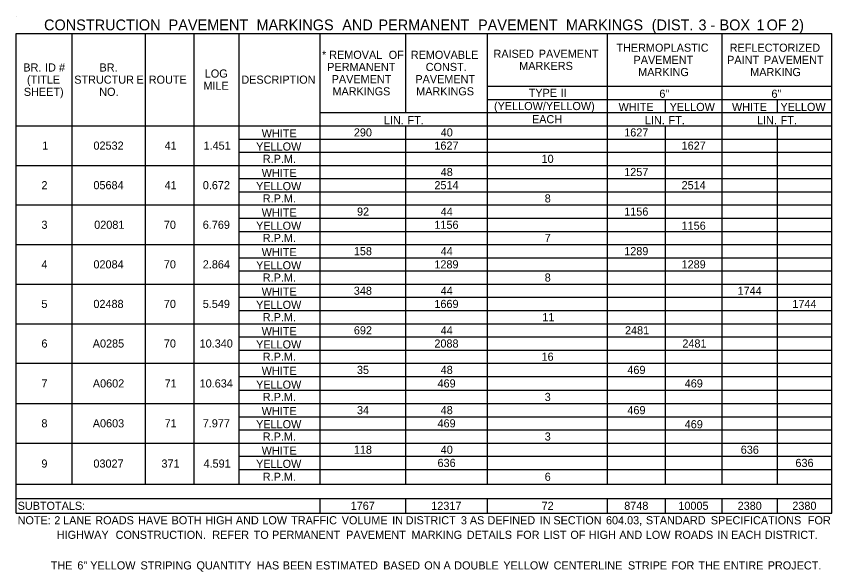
# Model space of a CAD drawing. Extents: x 544478 to 1930787, y -1948294 to 596640.
# Drawn here: x 557631 to 558234, y -1946545 to -1946135 of the extents above; entities that cross this region are included whole.
import ezdxf

# ---------------------------------------------------------------- set-up
doc = ezdxf.new("R2010")
doc.units = 0
doc.layers.add('Default', color=7, linetype='Continuous')

msp = doc.modelspace()

# ---------------------------------------------------------------- linework, layer by layer
at = {"layer": 'Default'}
for p, q in [((557631.45, -1946134.91), (557631.45, -1946134.91)), ((557631.45, -1946147.59), (558234.48, -1946147.59)), ((557631.45, -1946147.59), (557856.18, -1946147.59)), ((557631.45, -1946502), (557631.45, -1946147.59)), ((557672.88, -1946480.55), (557672.88, -1946147.59)), ((557727, -1946480.55), (557727, -1946147.59)), ((557763.07, -1946480.55), (557763.07, -1946147.59)), ((557796.22, -1946480.55), (557796.22, -1946147.59)), ((557856.18, -1946480.55), (557856.18, -1946147.59)), ((557919.56, -1946147.59), (557980.01, -1946147.59)), ((557919.56, -1946206.09), (557919.56, -1946147.59)), ((557980.01, -1946480.55), (557980.01, -1946147.59)), ((558068.73, -1946480.55), (558068.73, -1946147.59)), ((558153.56, -1946215.84), (558153.56, -1946147.59)), ((558153.56, -1946480.55), (558153.56, -1946147.59)), ((558234.48, -1946502), (558234.48, -1946147.59)), ((557980.01, -1946186.59), (558234.48, -1946186.59)), ((557980.01, -1946196.34), (558234.48, -1946196.34)), ((558111.63, -1946206.09), (558111.63, -1946196.34)), ((558194.51, -1946206.09), (558194.51, -1946196.34)), ((557856.18, -1946206.09), (558234.48, -1946206.09)), ((558068.73, -1946264.59), (558068.73, -1946206.09)), ((557631.45, -1946215.84), (557856.18, -1946215.84)), ((557631.45, -1946215.84), (557796.22, -1946215.84)), ((557796.22, -1946215.84), (558234.48, -1946215.84)), ((557919.56, -1946235.34), (557919.56, -1946215.84)), ((557919.56, -1946480.55), (557919.56, -1946215.84)), ((557980.01, -1946215.84), (558234.48, -1946215.84)), ((558111.63, -1946450.32), (558111.63, -1946215.84)), ((558111.63, -1946480.55), (558111.63, -1946215.84)), ((558194.51, -1946450.32), (558194.51, -1946215.84)), ((558194.51, -1946480.55), (558194.51, -1946215.84)), ((557796.22, -1946225.59), (558234.48, -1946225.59)), ((557796.22, -1946480.55), (557796.22, -1946225.59)), ((557856.18, -1946235.34), (557856.18, -1946225.59)), ((557796.22, -1946235.34), (558234.48, -1946235.34)), ((557631.45, -1946245.09), (557980.01, -1946245.09)), ((557796.22, -1946245.09), (557856.18, -1946245.09)), ((557856.18, -1946264.59), (557856.18, -1946245.09)), ((557919.56, -1946245.09), (557980.01, -1946245.09)), ((557919.56, -1946264.59), (557919.56, -1946245.09)), ((557980.01, -1946245.09), (558234.48, -1946245.09)), ((557980.01, -1946264.59), (557980.01, -1946245.09)), ((557796.22, -1946254.84), (558234.48, -1946254.84)), ((557796.22, -1946264.59), (558234.48, -1946264.59)), ((557631.45, -1946274.34), (558234.48, -1946274.34)), ((557796.22, -1946274.34), (557856.18, -1946274.34)), ((557856.18, -1946293.84), (557856.18, -1946274.34)), ((557919.56, -1946293.84), (557919.56, -1946274.34)), ((558068.73, -1946293.84), (558068.73, -1946274.34)), ((557796.22, -1946284.09), (558234.48, -1946284.09)), ((557796.22, -1946293.84), (558234.48, -1946293.84)), ((557631.45, -1946303.59), (558234.48, -1946303.59)), ((557856.18, -1946323.09), (557856.18, -1946303.59)), ((557919.56, -1946323.09), (557919.56, -1946303.59)), ((558068.73, -1946352.34), (558068.73, -1946303.59)), ((557796.22, -1946313.34), (558234.48, -1946313.34)), ((557796.22, -1946323.09), (558234.48, -1946323.09)), ((557631.45, -1946332.84), (557980.01, -1946332.84)), ((557796.22, -1946332.84), (557856.18, -1946332.84)), ((557856.18, -1946352.34), (557856.18, -1946332.84)), ((557919.56, -1946332.84), (557980.01, -1946332.84)), ((557919.56, -1946352.34), (557919.56, -1946332.84)), ((557980.01, -1946332.84), (558234.48, -1946332.84)), ((557796.22, -1946342.59), (558234.48, -1946342.59)), ((557980.01, -1946352.34), (557980.01, -1946342.59)), ((557796.22, -1946352.34), (558234.48, -1946352.34)), ((557631.45, -1946362.09), (558234.48, -1946362.09)), ((557856.18, -1946381.59), (557856.18, -1946362.09)), ((557919.56, -1946381.59), (557919.56, -1946362.09)), ((558068.73, -1946440.57), (558068.73, -1946362.09)), ((557796.22, -1946371.84), (558234.48, -1946371.84)), ((557980.01, -1946381.59), (557980.01, -1946371.84)), ((557796.22, -1946381.59), (558234.48, -1946381.59)), ((557631.45, -1946391.34), (557980.01, -1946391.34)), ((557856.18, -1946411.32), (557856.18, -1946391.34)), ((557919.56, -1946391.34), (557980.01, -1946391.34)), ((557919.56, -1946411.32), (557919.56, -1946391.34)), ((557980.01, -1946391.34), (558234.48, -1946391.34)), ((557796.22, -1946401.09), (558234.48, -1946401.09)), ((557980.01, -1946411.32), (557980.01, -1946401.09)), ((557796.22, -1946411.32), (558234.48, -1946411.32)), ((557631.45, -1946421.07), (557980.01, -1946421.07)), ((557796.22, -1946421.07), (557856.18, -1946421.07)), ((557856.18, -1946440.57), (557856.18, -1946421.07)), ((557919.56, -1946421.07), (557980.01, -1946421.07)), ((557919.56, -1946440.57), (557919.56, -1946421.07)), ((557980.01, -1946421.07), (558234.48, -1946421.07)), ((557796.22, -1946430.82), (558234.48, -1946430.82)), ((557796.22, -1946440.57), (558234.48, -1946440.57)), ((557631.45, -1946450.32), (558234.48, -1946450.32)), ((557856.18, -1946469.82), (557856.18, -1946450.32)), ((557919.56, -1946469.82), (557919.56, -1946450.32)), ((558068.73, -1946480.55), (558068.73, -1946450.32)), ((558153.56, -1946480.55), (558153.56, -1946450.32)), ((557796.22, -1946460.07), (558234.48, -1946460.07)), ((557796.22, -1946469.82), (558234.48, -1946469.82)), ((558111.63, -1946480.55), (558111.63, -1946469.82)), ((558194.51, -1946480.55), (558194.51, -1946469.82)), ((557631.45, -1946480.55), (558234.48, -1946480.55)), ((557919.56, -1946480.55), (557980.01, -1946480.55)), ((557980.01, -1946480.55), (558234.48, -1946480.55)), ((557631.45, -1946491.27), (558234.48, -1946491.27)), ((557856.18, -1946502), (557856.18, -1946491.27)), ((557856.18, -1946502), (557856.18, -1946491.27)), ((557919.56, -1946502), (557919.56, -1946491.27)), ((557919.56, -1946502), (557919.56, -1946491.27)), ((557980.01, -1946502), (557980.01, -1946491.27)), ((557980.01, -1946502), (557980.01, -1946491.27)), ((558068.73, -1946502), (558068.73, -1946491.27)), ((558068.73, -1946502), (558068.73, -1946491.27)), ((558111.63, -1946502), (558111.63, -1946491.27)), ((558111.63, -1946502), (558111.63, -1946491.27)), ((558153.56, -1946502), (558153.56, -1946491.27)), ((558153.56, -1946502), (558153.56, -1946491.27)), ((558194.51, -1946502), (558194.51, -1946491.27)), ((558194.51, -1946502), (558194.51, -1946491.27)), ((557631.45, -1946502), (558234.48, -1946502))]:
    msp.add_line(p, q, dxfattribs=at)

# ---------------------------------------------------------------- texts
for s, height, p in [('CONSTRUCTION', 8, (557651.97, -1946145.25)), (' PAVEMENT', 8, (557741.12, -1946145.25)), (' MARKINGS', 8, (557806.11, -1946145.25)), (' AND', 8, (557869.52, -1946145.25)), (' PERMANENT', 8, (557896.29, -1946145.25)), (' PAVEMENT', 8, (557969.97, -1946145.25)), (' MARKINGS', 8, (558034.96, -1946145.25)), (' (DIST.', 8, (558098.37, -1946145.25)), (' 3', 8, (558132.99, -1946145.25)), (' BOX', 8, (558148.57, -1946145.25)), (' 1', 8, (558175.89, -1946145.25)), (' OF', 8, (558183.4, -1946145.25)), (' 2)', 8, (558201.51, -1946145.25)), (' -', 8, (558141.83, -1946145.25)), ('THERMOPLASTIC', 6, (558075.26, -1946161.09)), ('REFLECTORIZED', 6, (558159.06, -1946161.09)), ('*', 6, (557857.54, -1946166.34)), (' REMOVAL', 6, (557860.62, -1946166.34)), (' OF', 6, (557904.62, -1946166.34)), ('REMOVABLE', 6, (557923.21, -1946166.34)), ('RAISED', 6, (557984.37, -1946165.59)), (' PAVEMENT', 6, (558015.63, -1946165.59)), ('PAVEMENT', 6, (558087.94, -1946170.09)), ('PAINT', 6, (558157.16, -1946170.09)), (' PAVEMENT', 6, (558182.14, -1946170.09)), ('BR.', 6, (557636.64, -1946175.71)), (' ID', 6, (557650.5, -1946175.71)), (' #', 6, (557660.8, -1946175.71)), ('BR.', 6, (557693.01, -1946175.71)), ('PERMANENT', 6, (557861.41, -1946175.34)), ('CONST.', 6, (557934.24, -1946175.34)), ('MARKERS', 6, (558003.38, -1946174.59)), ('LOG', 6, (557770.82, -1946180.21)), ('MARKING', 6, (558091.37, -1946179.09)), ('MARKING', 6, (558174.25, -1946179.09)), ('(TITLE', 6, (557639.34, -1946184.71)), ('STRUCTUR', 6, (557674.32, -1946184.71)), ('E', 6, (557720.39, -1946184.71)), ('ROUTE', 6, (557729.41, -1946184.71)), ('DESCRIPTION', 6, (557797.89, -1946184.71)), ('PAVEMENT', 6, (557864.67, -1946184.34)), ('PAVEMENT', 6, (557926.58, -1946184.34)), ('SHEET)', 6, (557637.01, -1946193.71)), ('NO.', 6, (557692.78, -1946193.71)), ('MILE', 6, (557769.84, -1946189.21)), ('MARKINGS', 6, (557865.26, -1946193.34)), ('MARKINGS', 6, (557927.17, -1946193.34)), ('TYPE', 6, (558010.41, -1946194.46)), (' II', 6, (558031.89, -1946194.46)), ('6"', 6, (558107.04, -1946195.14)), ('6"', 6, (558189.91, -1946195.14)), ('(YELLOW/YELLOW)', 6, (557984.77, -1946204.21)), ('WHITE', 6, (558076.89, -1946204.89)), ('YELLOW', 6, (558114.67, -1946204.89)), ('WHITE', 6, (558160.74, -1946204.89)), ('YELLOW', 6, (558196.57, -1946204.89)), ('LIN.', 6, (557903.31, -1946214.64)), (' FT.', 6, (557918.56, -1946214.64)), ('EACH', 6, (558012.82, -1946213.96)), ('LIN.', 6, (558096.36, -1946214.64)), (' FT.', 6, (558111.61, -1946214.64)), ('LIN.', 6, (558179.23, -1946214.64)), (' FT.', 6, (558194.49, -1946214.64)), ('WHITE', 6, (557812.92, -1946224.39)), ('290', 6, (557881.08, -1946223.71)), ('40', 6, (557945.33, -1946223.71)), ('1627', 6, (558081.05, -1946223.71)), ('1', 6, (557650.61, -1946233.46)), ('02532', 6, (557688.51, -1946233.46)), ('41', 6, (557741.14, -1946233.46)), ('1.451', 6, (557769.93, -1946233.46)), ('YELLOW', 6, (557808.78, -1946234.14)), ('1627', 6, (557940.65, -1946233.46)), ('1627', 6, (558123.47, -1946233.46)), ('10', 6, (558019.91, -1946243.21)), ('R.P.M.', 6, (557813.76, -1946243.21)), ('WHITE', 6, (557812.92, -1946253.64)), ('48', 6, (557945.31, -1946252.96)), ('1257', 6, (558081.05, -1946252.96)), ('2', 6, (557650.06, -1946262.71)), ('05684', 6, (557688.49, -1946262.71)), ('41', 6, (557741.14, -1946262.71)), ('0.672', 6, (557769.38, -1946262.71)), ('YELLOW', 6, (557808.78, -1946263.39)), ('2514', 6, (557940.67, -1946262.71)), ('2514', 6, (558123.48, -1946262.71)), ('R.P.M.', 6, (557813.76, -1946272.46)), ('8', 6, (558022.23, -1946272.46)), ('WHITE', 6, (557812.92, -1946282.89)), ('92', 6, (557883.43, -1946282.21)), ('44', 6, (557945.33, -1946282.21)), ('1156', 6, (558081.05, -1946282.21)), ('3', 6, (557650.03, -1946291.96)), ('02081', 6, (557689.06, -1946291.96)), ('70', 6, (557740.58, -1946291.96)), ('6.769', 6, (557769.35, -1946291.96)), ('YELLOW', 6, (557808.78, -1946292.64)), ('1156', 6, (557940.65, -1946291.96)), ('1156', 6, (558123.47, -1946292.64)), ('R.P.M.', 6, (557813.76, -1946301.71)), ('7', 6, (558022.23, -1946301.71)), ('WHITE', 6, (557812.92, -1946312.14)), ('158', 6, (557881.07, -1946311.46)), ('44', 6, (557945.33, -1946311.46)), ('1289', 6, (558081.05, -1946311.46)), ('4', 6, (557650.04, -1946321.21)), ('02084', 6, (557688.49, -1946321.21)), ('70', 6, (557740.58, -1946321.21)), ('2.864', 6, (557769.37, -1946321.21)), ('1289', 6, (557940.65, -1946321.21)), ('1289', 6, (558123.46, -1946321.21)), ('YELLOW', 6, (557808.78, -1946321.89)), ('R.P.M.', 6, (557813.76, -1946330.96)), ('8', 6, (558022.23, -1946330.96)), ('WHITE', 6, (557812.92, -1946341.39)), ('348', 6, (557881.07, -1946340.71)), ('44', 6, (557945.33, -1946340.71)), ('1744', 6, (558164.92, -1946340.71)), ('5', 6, (557650, -1946350.46)), ('02488', 6, (557688.48, -1946350.46)), ('70', 6, (557740.58, -1946350.46)), ('5.549', 6, (557769.35, -1946350.46)), ('YELLOW', 6, (557808.78, -1946351.14)), ('1669', 6, (557940.65, -1946350.46)), ('1744', 6, (558205.38, -1946350.46)), ('R.P.M.', 6, (557813.76, -1946360.21)), ('11', 6, (558020.48, -1946360.21)), ('WHITE', 6, (557812.92, -1946370.64)), ('692', 6, (557881.1, -1946369.96)), ('44', 6, (557945.33, -1946369.96)), ('2481', 6, (558081.63, -1946369.96)), ('6', 6, (557650.03, -1946379.71)), ('A0285', 6, (557687.99, -1946379.71)), ('70', 6, (557740.58, -1946379.71)), ('10.340', 6, (557767.03, -1946379.71)), ('YELLOW', 6, (557808.78, -1946380.39)), ('2088', 6, (557940.65, -1946379.71)), ('2481', 6, (558124.05, -1946379.71)), ('R.P.M.', 6, (557813.76, -1946389.46)), ('16', 6, (558019.9, -1946389.46)), ('WHITE', 6, (557812.92, -1946399.89)), ('35', 6, (557883.38, -1946399.21)), ('48', 6, (557945.31, -1946399.21)), ('469', 6, (558083.38, -1946399.21)), ('7', 6, (557650.03, -1946409.21)), ('A0602', 6, (557688.05, -1946409.21)), ('71', 6, (557741.14, -1946409.21)), ('10.634', 6, (557767.04, -1946409.21)), ('YELLOW', 6, (557808.78, -1946410.12)), ('469', 6, (557942.98, -1946409.21)), ('469', 6, (558125.79, -1946409.21)), ('R.P.M.', 6, (557813.76, -1946419.2)), ('3', 6, (558022.23, -1946419.2)), ('WHITE', 6, (557812.92, -1946429.62)), ('34', 6, (557883.42, -1946428.95)), ('48', 6, (557945.31, -1946428.95)), ('469', 6, (558083.38, -1946428.95)), ('8', 6, (557650.02, -1946438.7)), ('A0603', 6, (557688.01, -1946438.7)), ('71', 6, (557741.14, -1946438.7)), ('7.977', 6, (557769.35, -1946438.7)), ('YELLOW', 6, (557808.78, -1946439.37)), ('469', 6, (557942.98, -1946438.7)), ('469', 6, (558125.79, -1946439.37)), ('R.P.M.', 6, (557813.76, -1946448.45)), ('3', 6, (558022.23, -1946448.45)), ('WHITE', 6, (557812.92, -1946458.87)), ('118', 6, (557881.07, -1946458.2)), ('40', 6, (557945.33, -1946458.2)), ('636', 6, (558167.23, -1946458.2)), ('9', 6, (557650.02, -1946468.44)), ('03027', 6, (557688.48, -1946468.44)), ('371', 6, (557738.81, -1946468.44)), ('4.591', 6, (557769.93, -1946468.44)), ('YELLOW', 6, (557808.78, -1946468.62)), ('636', 6, (557942.98, -1946467.95)), ('636', 6, (558207.7, -1946467.95)), ('R.P.M.', 6, (557813.76, -1946478.19)), ('6', 6, (558022.23, -1946478.19)), ('SUBTOTALS:', 6, (557632.42, -1946499.64)), ('1767', 6, (557878.74, -1946499.64)), ('12317', 6, (557938.32, -1946499.64)), ('72', 6, (558019.92, -1946499.64)), ('8748', 6, (558081.05, -1946499.64)), ('10005', 6, (558121.07, -1946499.64)), ('2380', 6, (558164.92, -1946499.64)), ('2380', 6, (558205.38, -1946499.64)), ('NOTE:', 6, (557632.42, -1946510.36)), (' 2', 6, (557657.31, -1946510.36)), (' LANE', 6, (557663.85, -1946510.36)), (' ROADS', 6, (557687.63, -1946510.36)), (' HAVE', 6, (557719.34, -1946510.36)), (' BOTH', 6, (557744.05, -1946510.36)), (' HIGH', 6, (557768.99, -1946510.36)), (' AND', 6, (557791.6, -1946510.36)), (' LOW', 6, (557811.19, -1946510.36)), (' TRAFFIC', 6, (557832.51, -1946510.36)), (' VOLUME', 6, (557869.9, -1946510.36)), (' IN', 6, (557907.19, -1946510.36)), (' DISTRICT', 6, (557917.21, -1946510.36)), (' 3', 6, (557958.03, -1946510.36)), (' AS', 6, (557964.64, -1946510.36)), (' DEFINED', 6, (557977.71, -1946510.36)), (' IN', 6, (558016.39, -1946510.36)), (' SECTION', 6, (558026.41, -1946510.36)), (' 604.03,', 6, (558065.32, -1946510.36)), (' STANDARD', 6, (558094.86, -1946510.36)), (' SPECIFICATIONS', 6, (558142.86, -1946510.36)), (' FOR', 6, (558214.63, -1946510.36)), ('             HIGHWAY', 6, (557632.42, -1946521.09)), (' CONSTRUCTION.', 6, (557702.67, -1946521.09)), (' REFER', 6, (557774.14, -1946521.09)), (' TO', 6, (557804.77, -1946521.09)), (' PERMANENT', 6, (557818.36, -1946521.09)), (' PAVEMENT', 6, (557873.16, -1946521.09)), (' MARKING', 6, (557921.45, -1946521.09)), (' DETAILS', 6, (557962.38, -1946521.09)), (' FOR', 6, (557999.21, -1946521.09)), (' LIST', 6, (558019.12, -1946521.09)), (' OF', 6, (558038.98, -1946521.09)), (' HIGH', 6, (558052.57, -1946521.09)), (' AND', 6, (558075.18, -1946521.09)), (' LOW', 6, (558094.76, -1946521.09)), (' ROADS', 6, (558116.08, -1946521.09)), (' IN', 6, (558147.79, -1946521.09)), (' EACH', 6, (558157.82, -1946521.09)), (' DISTRICT.', 6, (558182.76, -1946521.09)), ('           THE', 6, (557632.42, -1946543.7)), (' 6"', 6, (557674.35, -1946543.7)), (' YELLOW', 6, (557683.92, -1946543.7)), (' STRIPING', 6, (557721.09, -1946543.7)), (' QUANTITY', 6, (557762.49, -1946543.7)), (' HAS', 6, (557807.14, -1946543.7)), (' BEEN', 6, (557826.27, -1946543.7)), (' ESTIMATED', 6, (557850.74, -1946543.7)), (' BASED', 6, (557900.61, -1946543.7)), (' ON', 6, (557930.91, -1946543.7)), (' A', 6, (557945.13, -1946543.7)), (' DOUBLE', 6, (557953.07, -1946543.7)), (' YELLOW', 6, (557989.42, -1946543.7)), (' CENTERLINE', 6, (558026.59, -1946543.7)), (' STRIPE', 6, (558081.58, -1946543.7)), (' FOR', 6, (558113.74, -1946543.7)), (' THE', 6, (558133.65, -1946543.7)), (' ENTIRE', 6, (558152.3, -1946543.7)), (' PROJECT.', 6, (558184.93, -1946543.7))]:
    msp.add_text(s, height=height, dxfattribs=at).set_placement(p)

doc.saveas('drawing.dxf')
